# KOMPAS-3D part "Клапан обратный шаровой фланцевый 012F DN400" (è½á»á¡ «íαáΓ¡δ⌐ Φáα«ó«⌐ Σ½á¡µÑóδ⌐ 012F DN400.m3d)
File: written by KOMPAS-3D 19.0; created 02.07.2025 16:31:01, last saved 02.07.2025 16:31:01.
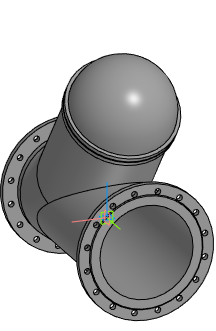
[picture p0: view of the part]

Document properties: Полное имя файла: E:\Dendor Работа Сачек\3D для проектировщиков\5.3 Тип 012F, 012F.Z Клапан обратный шаровой фланцевый\stp_Клапан обратный шаровой фланцевый 012F\Клапан обратный шаровой фланцевый 012F DN400.m3d

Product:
- Part/product: Клапан обратный шаровой фланцевый 012F DN400

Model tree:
1. Операция без истории:1  (labels: Клапан обратный шаровой фланцевый 012F DN400)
